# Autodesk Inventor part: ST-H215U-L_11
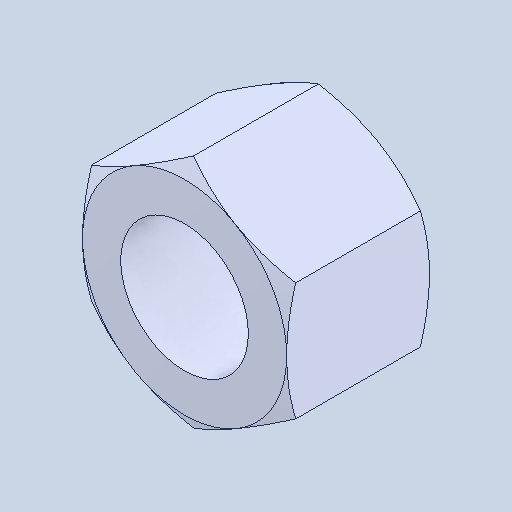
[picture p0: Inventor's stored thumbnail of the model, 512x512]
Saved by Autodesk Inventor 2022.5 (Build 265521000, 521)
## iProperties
Created: 2024-07
Part Number: ST-H215U-L_11
Material: 一般
Document SubType Name: Modeling
Designer: ImaoCorp
Density: 1 g/cm^3
Appearance: 既定
Author: ImaoCorp
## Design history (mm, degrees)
feature "ST-H215U-L_11"
node "ソリッド1"
